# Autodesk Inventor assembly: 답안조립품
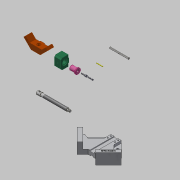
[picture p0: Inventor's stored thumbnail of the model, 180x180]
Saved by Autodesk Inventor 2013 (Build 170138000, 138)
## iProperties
Created: 2019-04
Part Number: 답안조립품
Document SubType Name: Assembly
Designer: Administrator
Author: Administrator
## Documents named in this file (11)
- C:\Users\Administrator\Desktop\490407V1026\답안조립품.iam
- C:\Users\Administrator\Desktop\490407V1026\베이스.ipt
- C:\Users\Administrator\Desktop\490407V1026\리드스크류.ipt
- C:\Users\Administrator\Desktop\490407V1026\멈춤나사 M4x5.ipt
- C:\Users\Administrator\Desktop\490407V1026\멈춤나사 M4x10.ipt
- C:\Users\Administrator\Desktop\490407V1026\볼트 M4x16.ipt
- C:\Users\Administrator\Desktop\490407V1026\부시.ipt
- C:\Users\Administrator\Desktop\490407V1026\서포트.ipt
- C:\Users\Administrator\Desktop\490407V1026\조.ipt
- C:\Users\Administrator\Desktop\490407V1026\평행 핀 2.5x24.ipt
- C:\Users\Administrator\Desktop\490407V1026\핸들.ipt
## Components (1 placed, 1 different names)
1. 핸들:1
